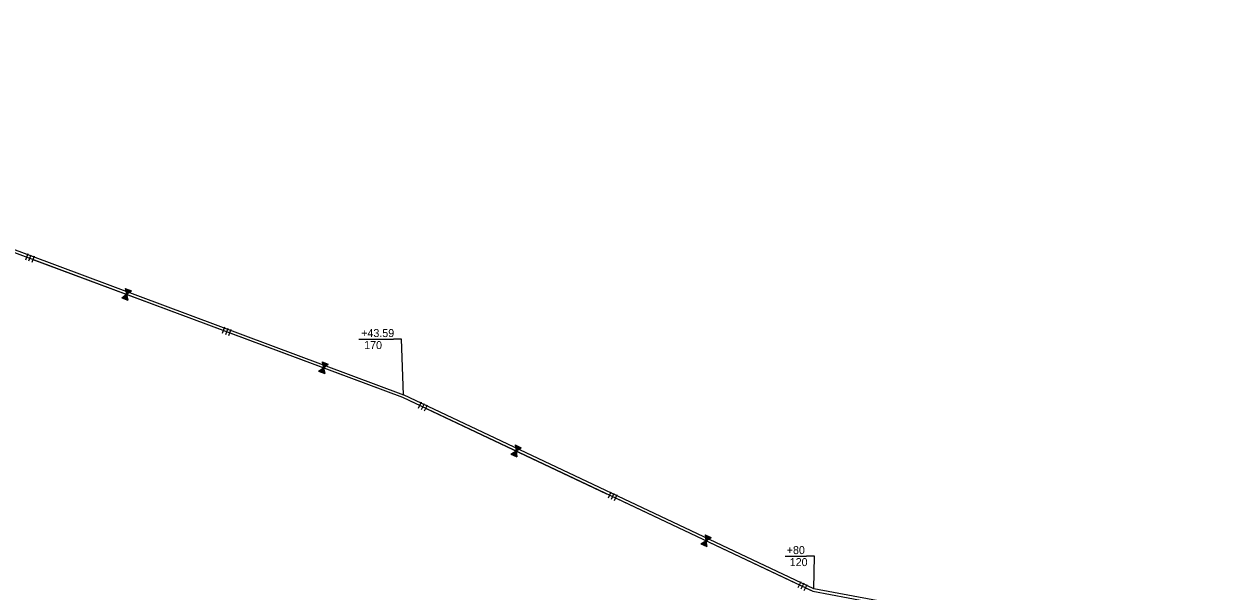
# Model space of a CAD drawing. Extents: x 979729 to 993523, y 1834148 to 1845433.
# Drawn here: x 981898 to 982788, y 1838276 to 1838701 of the extents above; entities that cross this region are included whole.
import ezdxf

# ---------------------------------------------------------------- set-up
doc = ezdxf.new("R2010")
doc.units = 0
for name, color, linetype in [('42', 7, 'Continuous'), ('51', 7, 'Continuous'), ('R_Draft', 7, 'Continuous')]:
    doc.layers.add(name, color=color, linetype=linetype)

msp = doc.modelspace()

# ---------------------------------------------------------------- linework, layer by layer
at = {"layer": '42'}
for p, q in [((981663.1, 1838614.53), (982182.52, 1838420.85)), ((981901.46, 1838528.32), (981899.71, 1838523.63)), ((981903.8, 1838527.45), (981902.05, 1838522.76)), ((981906.14, 1838526.57), (981904.4, 1838521.89)), ((981971.89, 1838495.39), (981975.54, 1838498.03)), ((981973.28, 1838496.37), (981973.67, 1838494.72)), ((981973.52, 1838496.44), (981973.91, 1838494.78)), ((981973.72, 1838496.66), (981974.23, 1838494.51)), ((981973.95, 1838496.8), (981974.51, 1838494.41)), ((981974.16, 1838497), (981974.79, 1838494.3)), ((981974.39, 1838497.11), (981975.07, 1838494.2)), ((981974.51, 1838502.41), (981975.54, 1838498.03)), ((981974.54, 1838502.34), (981974.6, 1838502.38)), ((981974.6, 1838497.32), (981975.36, 1838494.09)), ((981974.62, 1838502.09), (981974.88, 1838502.28)), ((981974.67, 1838501.82), (981975.16, 1838502.17)), ((981974.75, 1838501.56), (981975.44, 1838502.07)), ((981974.79, 1838501.29), (981975.72, 1838501.96)), ((981974.82, 1838497.46), (981975.64, 1838493.99)), ((981974.84, 1838501.01), (981976.01, 1838501.86)), ((981974.92, 1838500.76), (981976.29, 1838501.75)), ((981975.04, 1838497.64), (981975.92, 1838493.88)), ((981975.05, 1838500.55), (981976.43, 1838501.55)), ((981975.06, 1838500.25), (981976.85, 1838501.54)), ((981975.14, 1838500), (981977.13, 1838501.44)), ((981975.17, 1838499.71), (981977.41, 1838501.33)), ((981975.27, 1838499.47), (981977.69, 1838501.23)), ((981975.27, 1838497.75), (981976.2, 1838493.78)), ((981975.29, 1838499.18), (981977.98, 1838501.12)), ((981975.37, 1838498.93), (981978.26, 1838501.02)), ((981975.41, 1838498.65), (981978.54, 1838500.91)), ((981975.47, 1838497.95), (981976.48, 1838493.67)), ((981975.52, 1838498.42), (981978.82, 1838500.81)), ((981975.54, 1838498.13), (981979.1, 1838500.7)), ((981975.54, 1838498.03), (981979.2, 1838500.67)), ((981975.54, 1838498.03), (981976.57, 1838493.64)), ((981971.96, 1838495.42), (981971.98, 1838495.35)), ((981972.19, 1838495.56), (981972.26, 1838495.25)), ((981972.4, 1838495.73), (981972.54, 1838495.14)), ((981972.63, 1838495.87), (981972.82, 1838495.04)), ((981972.84, 1838496.05), (981973.1, 1838494.93)), ((981973.06, 1838496.23), (981973.39, 1838494.83)), ((982049.03, 1838473.29), (982047.28, 1838468.61)), ((982051.37, 1838472.42), (982049.63, 1838467.73)), ((982053.72, 1838471.54), (982051.97, 1838466.86)), ((982119.46, 1838440.36), (982123.12, 1838443)), ((982122.08, 1838447.39), (982123.12, 1838443)), ((982122.12, 1838447.31), (982122.17, 1838447.35)), ((982122.2, 1838447.06), (982122.45, 1838447.25)), ((982122.24, 1838446.79), (982122.73, 1838447.14)), ((982122.32, 1838446.54), (982123.02, 1838447.04)), ((982122.37, 1838446.26), (982123.3, 1838446.93)), ((982122.41, 1838445.99), (982123.58, 1838446.83)), ((982122.49, 1838445.73), (982123.86, 1838446.72)), ((982122.62, 1838445.52), (982124.01, 1838446.52)), ((982122.64, 1838445.22), (982124.42, 1838446.51)), ((982122.72, 1838444.97), (982124.71, 1838446.41)), ((982122.74, 1838444.68), (982124.99, 1838446.3)), ((982122.84, 1838444.44), (982125.27, 1838446.2)), ((982122.86, 1838444.15), (982125.55, 1838446.09)), ((982122.94, 1838443.9), (982125.83, 1838445.99)), ((982122.99, 1838443.63), (982126.11, 1838445.88)), ((982123.05, 1838442.93), (982124.06, 1838438.65)), ((982123.09, 1838443.39), (982126.39, 1838445.78)), ((982123.11, 1838443.1), (982126.68, 1838445.67)), ((982123.12, 1838443), (982126.77, 1838445.64)), ((982123.12, 1838443), (982124.15, 1838438.61)), ((982119.54, 1838440.39), (982119.55, 1838440.33)), ((982119.76, 1838440.53), (982119.83, 1838440.22)), ((982119.97, 1838440.71), (982120.11, 1838440.12)), ((982120.2, 1838440.84), (982120.4, 1838440.01)), ((982120.41, 1838441.02), (982120.68, 1838439.91)), ((982120.63, 1838441.2), (982120.96, 1838439.8)), ((982120.85, 1838441.34), (982121.24, 1838439.7)), ((982121.09, 1838441.42), (982121.48, 1838439.75)), ((982121.3, 1838441.63), (982121.8, 1838439.49)), ((982121.52, 1838441.77), (982122.09, 1838439.38)), ((982121.73, 1838441.97), (982122.37, 1838439.28)), ((982121.96, 1838442.09), (982122.65, 1838439.17)), ((982122.17, 1838442.29), (982122.93, 1838439.07)), ((982122.39, 1838442.43), (982123.21, 1838438.96)), ((982122.61, 1838442.61), (982123.49, 1838438.86)), ((982122.84, 1838442.72), (982123.77, 1838438.75)), ((982182.52, 1838420.85), (982490.19, 1838275.5)), ((982196.34, 1838417.08), (982194.2, 1838412.56)), ((982198.6, 1838416.02), (982196.46, 1838411.5)), ((982200.86, 1838414.95), (982198.72, 1838410.43)), ((982263.74, 1838378.33), (982267.61, 1838380.65)), ((982266.95, 1838385.11), (982267.61, 1838380.65)), ((982266.97, 1838385.04), (982267.03, 1838385.07)), ((982267.03, 1838384.78), (982267.3, 1838384.94)), ((982267.05, 1838384.5), (982267.57, 1838384.82)), ((982267.11, 1838384.25), (982267.85, 1838384.69)), ((982267.13, 1838383.97), (982268.12, 1838384.56)), ((982267.16, 1838383.69), (982268.39, 1838384.43)), ((982267.21, 1838383.43), (982268.66, 1838384.3)), ((982267.32, 1838382.91), (982269.2, 1838384.05)), ((982267.33, 1838383.21), (982268.79, 1838384.09)), ((982267.37, 1838382.65), (982269.48, 1838383.92)), ((982267.37, 1838382.36), (982269.75, 1838383.79)), ((982267.45, 1838382.12), (982270.02, 1838383.66)), ((982267.45, 1838381.82), (982270.29, 1838383.53)), ((982267.51, 1838381.57), (982270.56, 1838383.4)), ((982267.53, 1838381.29), (982270.83, 1838383.28)), ((982267.53, 1838380.59), (982268.17, 1838376.24)), ((982267.61, 1838381.05), (982271.11, 1838383.15)), ((982267.61, 1838380.75), (982271.38, 1838383.02)), ((982267.61, 1838380.65), (982271.47, 1838382.98)), ((982267.61, 1838380.65), (982268.26, 1838376.19)), ((982263.82, 1838378.36), (982263.83, 1838378.29)), ((982264.05, 1838378.47), (982264.1, 1838378.16)), ((982264.28, 1838378.63), (982264.37, 1838378.03)), ((982264.52, 1838378.75), (982264.64, 1838377.91)), ((982264.75, 1838378.91), (982264.91, 1838377.78)), ((982264.98, 1838379.07), (982265.19, 1838377.65)), ((982265.21, 1838379.19), (982265.46, 1838377.52)), ((982265.45, 1838379.25), (982265.7, 1838377.56)), ((982265.68, 1838379.44), (982266, 1838377.26)), ((982265.91, 1838379.56), (982266.27, 1838377.14)), ((982266.14, 1838379.75), (982266.54, 1838377.01)), ((982266.38, 1838379.84), (982266.82, 1838376.88)), ((982266.6, 1838380.03), (982267.09, 1838376.75)), ((982266.84, 1838380.15), (982267.36, 1838376.62)), ((982267.07, 1838380.31), (982267.63, 1838376.49)), ((982267.31, 1838380.4), (982267.9, 1838376.37)), ((982338.75, 1838349.81), (982336.61, 1838345.29)), ((982341.01, 1838348.74), (982338.87, 1838344.22)), ((982343.27, 1838347.68), (982341.13, 1838343.15)), ((982406.15, 1838311.06), (982410.01, 1838313.38)), ((982406.23, 1838311.08), (982406.24, 1838311.02)), ((982406.46, 1838311.2), (982406.51, 1838310.89)), ((982406.69, 1838311.36), (982406.78, 1838310.76)), ((982406.93, 1838311.48), (982407.05, 1838310.63)), ((982407.16, 1838311.64), (982407.32, 1838310.5)), ((982407.38, 1838311.8), (982407.6, 1838310.37)), ((982407.62, 1838311.92), (982407.87, 1838310.25)), ((982407.86, 1838311.97), (982408.11, 1838310.28)), ((982408.09, 1838312.17), (982408.41, 1838309.99)), ((982408.32, 1838312.29), (982408.68, 1838309.86)), ((982408.55, 1838312.48), (982408.95, 1838309.73)), ((982408.79, 1838312.57), (982409.23, 1838309.6)), ((982409.01, 1838312.75), (982409.5, 1838309.48)), ((982409.25, 1838312.87), (982409.77, 1838309.35)), ((982409.36, 1838317.84), (982410.01, 1838313.38)), ((982409.38, 1838317.76), (982409.44, 1838317.8)), ((982409.44, 1838317.51), (982409.71, 1838317.67)), ((982409.46, 1838317.23), (982409.98, 1838317.54)), ((982409.48, 1838313.03), (982410.04, 1838309.22)), ((982409.52, 1838316.97), (982410.26, 1838317.41)), ((982409.54, 1838316.69), (982410.53, 1838317.28)), ((982409.57, 1838316.42), (982410.8, 1838317.16)), ((982409.62, 1838316.16), (982411.07, 1838317.03)), ((982409.72, 1838313.12), (982410.31, 1838309.09)), ((982409.73, 1838315.93), (982411.2, 1838316.81)), ((982409.73, 1838315.64), (982411.61, 1838316.77)), ((982409.78, 1838315.38), (982411.89, 1838316.64)), ((982409.78, 1838315.09), (982412.16, 1838316.51)), ((982409.86, 1838314.84), (982412.43, 1838316.39)), ((982409.86, 1838314.55), (982412.7, 1838316.26)), ((982409.92, 1838314.29), (982412.97, 1838316.13)), ((982409.94, 1838314.02), (982413.24, 1838316)), ((982409.94, 1838313.31), (982410.58, 1838308.96)), ((982410.01, 1838313.38), (982413.88, 1838315.7)), ((982410.01, 1838313.38), (982410.67, 1838308.92)), ((982410.02, 1838313.77), (982413.52, 1838315.87)), ((982410.02, 1838313.48), (982413.79, 1838315.74)), ((982481.16, 1838282.54), (982479.02, 1838278.02)), ((982483.42, 1838281.47), (982481.28, 1838276.95)), ((982485.68, 1838280.4), (982483.54, 1838275.88)), ((982490.19, 1838275.5), (982851.26, 1838208.07))]:
    msp.add_line(p, q, dxfattribs=at)
for points in [[(981905.27, 1838524.23), (982045.82, 1838471.82)], [(981974.51, 1838502.41), (981979.2, 1838500.67)], [(981971.89, 1838495.39), (981976.57, 1838493.64)], [(982052.84, 1838469.2), (982182.52, 1838420.85), (982193.01, 1838415.89)], [(982122.08, 1838447.39), (982126.77, 1838445.64)], [(982119.46, 1838440.36), (982124.15, 1838438.61)], [(982199.79, 1838412.69), (982335.42, 1838348.62)], [(982266.95, 1838385.11), (982271.47, 1838382.98)], [(982263.74, 1838378.33), (982268.26, 1838376.19)], [(982342.2, 1838345.41), (982477.83, 1838281.34)], [(982406.15, 1838311.06), (982410.67, 1838308.92)], [(982409.36, 1838317.84), (982413.88, 1838315.7)], [(982484.61, 1838278.14), (982490.19, 1838275.5)]]:
    msp.add_lwpolyline(points, dxfattribs=at)
at = {"layer": '51'}
for points in [[(981283.24, 1838700.78), (981406.41, 1838642.88), (981663.56, 1838616.49), (982183.3, 1838422.69)], [(983839.63, 1837883.59), (982851.76, 1838210.02), (982490.82, 1838277.42), (982183.3, 1838422.69)]]:
    msp.add_lwpolyline(points, dxfattribs=at)
at = {"layer": 'R_Draft'}
for p, q in [((982149.69, 1838464.48), (982175.73, 1838464.48)), ((982469.54, 1838301.85), (982485.34, 1838301.85))]:
    msp.add_line(p, q, dxfattribs=at)
for points in [[(982183.3, 1838422.69), (982181.73, 1838464.48), (982175.73, 1838464.48)], [(982490.82, 1838277.42), (982491.34, 1838301.85), (982485.34, 1838301.85)]]:
    msp.add_lwpolyline(points, dxfattribs=at)

# ---------------------------------------------------------------- texts
for s, p in [('+43.59', (982151.46, 1838465.98)), (' 170', (982151.46, 1838456.98)), ('+80', (982470.62, 1838303.35)), (' 120', (982470.62, 1838294.35))]:
    msp.add_text(s, height=6, rotation=360, dxfattribs=at).set_placement(p)

doc.saveas('drawing.dxf')
